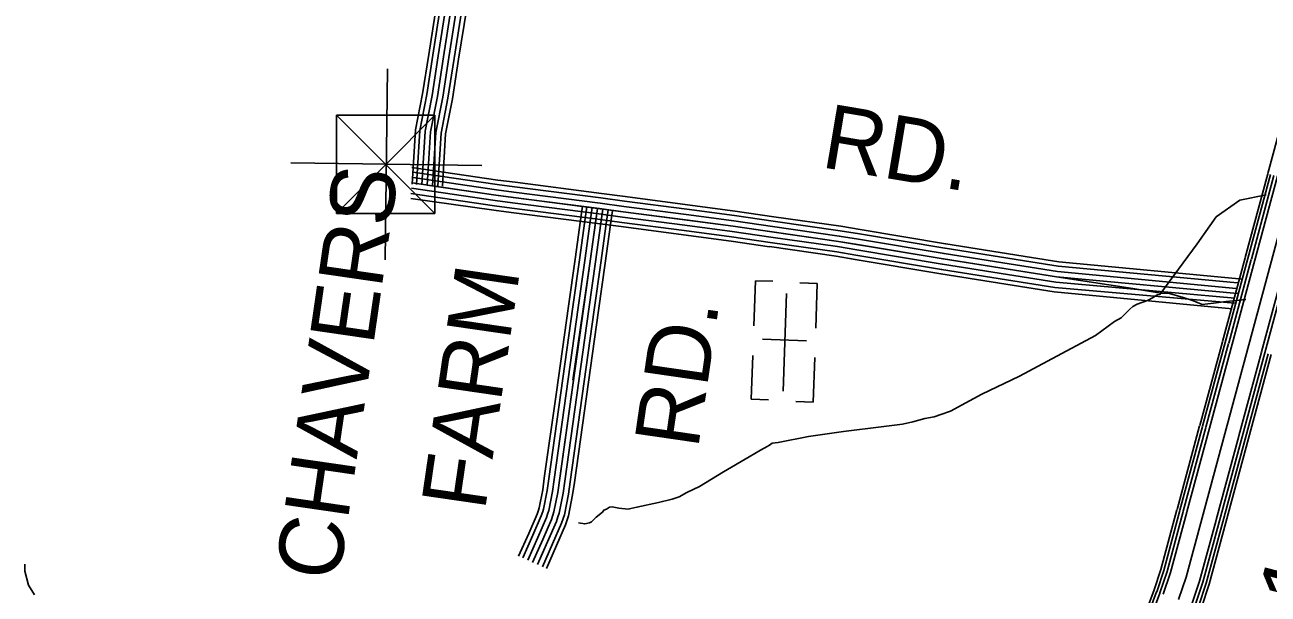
# Model space of a CAD drawing. Extents: x 1551132 to 1791609, y 378168 to 563823.
# Drawn here: x 1594362 to 1601513, y 424575 to 427854 of the extents above; entities that cross this region are included whole.
import ezdxf

# ---------------------------------------------------------------- set-up
doc = ezdxf.new("R2010")
doc.units = 0
for name, color, linetype in [('DESIGN - ROW - Right-of-Way and Easement Labels', 7, 'Continuous'), ('DESIGN - TRAFFIC CONTROL PERMANENT - Pavement Marking', 7, 'Continuous'), ('DESIGN - TRAFFIC CONTROL PERMANENT - Signalization', 7, 'Continuous'), ('DESIGN - TRANSPORTATION - Text', 7, 'Continuous'), ('DESIGN - UTILITIES - Cable (Underground) with Text', 7, 'Continuous'), ('SURVEY - CENTERLINE - Preliminary Text', 7, 'Continuous'), ('SURVEY - DRAINAGE - Bridge Hydraulic Data - Points - Locators', 7, 'Continuous'), ('SURVEY - PROPERTY - Owners', 7, 'Continuous'), ('SURVEY - TRANSPORTATION - Roads', 7, 'Continuous')]:
    doc.layers.add(name, color=color, linetype=linetype)

msp = doc.modelspace()

# ---------------------------------------------------------------- linework, layer by layer
at = {"layer": 'DESIGN - TRAFFIC CONTROL PERMANENT - Pavement Marking'}
for p, q in [((1596720.792, 427332.949), (1596155.091, 427332.935)), ((1596437.948, 427050.091), (1596155.091, 427332.935)), ((1596155.091, 427332.935), (1596155.105, 426767.233)), ((1596437.948, 427050.091), (1596720.792, 427332.949)), ((1596720.806, 426767.247), (1596720.792, 427332.949)), ((1596155.105, 426767.233), (1596437.948, 427050.091)), ((1596437.948, 427050.091), (1596720.806, 426767.247)), ((1596155.105, 426767.233), (1596720.806, 426767.247))]:
    msp.add_line(p, q, dxfattribs=at)
at = {"layer": 'DESIGN - TRANSPORTATION - Text'}
for points in [[(1597546.754, 424986.179), (1597582.628, 424979.612), (1597608.703, 424985.221), (1597620.786, 424991.038), (1597647.193, 425018.68), (1597683.626, 425048.173), (1597691.776, 425058.065), (1597707.859, 425063.831), (1597724.025, 425075.598), (1597740.041, 425077.357), (1597777.915, 425070.757), (1597831.781, 425063.915), (1597847.822, 425067.673), (1597881.921, 425075.165), (1598006.277, 425103.291), (1598084.517, 425122.116), (1598124.699, 425135.525), (1598169.065, 425160.884), (1598241.563, 425195.827), (1598380.776, 425279.829), (1598528.015, 425365.706), (1598592.58, 425404.783), (1598630.887, 425426.233), (1598644.995, 425434.025), (1598661.137, 425443.792), (1598695.203, 425449.284), (1598869.607, 425482.643), (1599069.927, 425511.602), (1599288.205, 425538.286), (1599410.378, 425554.429), (1599468.543, 425567.554), (1599538.791, 425586.505), (1599592.898, 425595.68), (1599631.081, 425609.114), (1599685.346, 425628.314), (1599774.044, 425677.032), (1599866.775, 425727.692), (1600082.229, 425830.553), (1600243.45, 425916.214), (1600519.569, 426064.218), (1600628.749, 426144.678), (1600667.057, 426166.129), (1600685.323, 426183.879), (1600717.789, 426215.43), (1600734.022, 426231.214), (1600760.213, 426244.831), (1600818.503, 426265.973), (1600852.753, 426283.474), (1600874.985, 426299.157), (1600891.002, 426300.916), (1601104.63, 426592.082), (1601213.628, 426747.228), (1601350.116, 426844.689), (1601502.063, 426874.673)], [(1594362.12, 424747.754), (1594361.67, 424707.703), (1594382.778, 424627.351), (1594416.144, 424570.883)]]:
    msp.add_lwpolyline(points, dxfattribs=at)
at = {"layer": 'DESIGN - UTILITIES - Cable (Underground) with Text'}
for p, q in [((1598563.915, 426380.045), (1598554.81, 426119.381)), ((1598663.534, 426376.572), (1598564.531, 426380.045)), ((1598919.931, 426363.683), (1598820.221, 426367.157)), ((1598910.868, 426107.069), (1598919.84, 426363.683)), ((1598858.284, 426034.466), (1598604.795, 426043.305)), ((1598548.87, 425948.527), (1598540.073, 425697.238)), ((1598895.998, 425680.834), (1598905.02, 425938.806)), ((1598540.206, 425697.238), (1598638.417, 425693.806)), ((1598895.823, 425680.834), (1598796.379, 425684.308))]:
    msp.add_line(p, q, dxfattribs=at)
msp.add_lwpolyline([(1598742.386, 426306.388), (1598722.727, 425743.708)], dxfattribs=at)
at = {"layer": 'SURVEY - CENTERLINE - Preliminary Text'}
for points in [[(1600998.398, 424544.753), (1601040.98, 424673.207), (1601887.204, 427811.148)], [(1601510.788, 426997.068), (1601640.985, 427479.831)], [(1601380.365, 426513.422), (1601510.554, 426996.184)], [(1601397.265, 426508.863), (1601527.454, 426991.626)], [(1601416.573, 426503.655), (1601546.762, 426986.418)], [(1601436.389, 426499.246), (1601566.578, 426982.017)], [(1601249.943, 426029.784), (1601380.132, 426512.547)], [(1601266.843, 426025.225), (1601397.032, 426507.988)], [(1601286.151, 426020.017), (1601416.339, 426502.78)], [(1601305.967, 426015.609), (1601436.156, 426498.371)], [(1601474.379, 425970.191), (1601604.568, 426452.954)], [(1601493.962, 425964.907), (1601624.151, 426447.67)], [(1601119.512, 425546.138), (1601249.701, 426028.901)], [(1601136.412, 425541.579), (1601266.601, 426024.342)], [(1601155.72, 425536.371), (1601285.909, 426019.134)], [(1601175.536, 425531.962), (1601305.733, 426014.734)], [(1601343.949, 425486.545), (1601474.146, 425969.316)], [(1601363.532, 425481.261), (1601493.729, 425964.032)], [(1601382.84, 425476.053), (1601513.037, 425958.824)], [(1601399.739, 425471.494), (1601529.936, 425954.265)], [(1600989.09, 425062.492), (1601119.279, 425545.263)], [(1601005.99, 425057.933), (1601136.179, 425540.704)], [(1601025.298, 425052.725), (1601155.487, 425535.496)], [(1601045.114, 425048.325), (1601175.303, 425531.087)], [(1601213.527, 425002.907), (1601343.716, 425485.67)], [(1601233.109, 424997.624), (1601363.298, 425480.386)], [(1601252.417, 424992.415), (1601382.606, 425475.178)], [(1601269.317, 424987.857), (1601399.506, 425470.619)], [(1600855.451, 424594.938), (1600855.56, 424595.221), (1600895.859, 424716.791), (1600988.849, 425061.617)], [(1600871.834, 424588.788), (1600872.059, 424589.388), (1600912.625, 424711.757), (1601005.748, 425057.058)], [(1600890.559, 424581.762), (1600890.926, 424582.721), (1600931.791, 424705.999), (1601025.056, 425051.85)], [(1600909.9, 424575.562), (1600910.067, 424576.012), (1600951.224, 424700.166), (1601044.881, 425047.441)], [(1601073.146, 424514.111), (1601074.538, 424517.811), (1601118.345, 424649.973), (1601213.293, 425002.024)], [(1601092.129, 424506.969), (1601093.662, 424511.044), (1601137.778, 424644.131), (1601232.876, 424996.74)], [(1601110.845, 424499.919), (1601112.52, 424504.377), (1601156.944, 424638.372), (1601252.184, 424991.532)], [(1601127.22, 424493.752), (1601129.02, 424498.535), (1601173.711, 424633.339), (1601269.084, 424986.973)], [(1600635.373, 424194.36), (1600709.038, 424294.738), (1600784.786, 424425.483), (1600816.744, 424492.193), (1600855.193, 424594.254)], [(1600649.481, 424184.002), (1600723.704, 424285.146), (1600800.269, 424417.3), (1600832.852, 424485.31), (1600871.568, 424588.088)], [(1600665.606, 424172.176), (1600740.462, 424274.188), (1600817.969, 424407.958), (1600851.268, 424477.451), (1600890.284, 424581.037)]]:
    msp.add_lwpolyline(points, dxfattribs=at)
at = {"layer": 'SURVEY - DRAINAGE - Bridge Hydraulic Data - Points - Locators'}
for p, q in [((1596448.465, 427600.864), (1596433.94, 426500.927)), ((1596991.143, 427043.633), (1595891.261, 427058.158))]:
    msp.add_line(p, q, dxfattribs=at)
at = {"layer": 'SURVEY - PROPERTY - Owners'}
for points in [[(1596675.742, 426930.705), (1596694.817, 427237.438), (1596734.408, 427441.635), (1596770.182, 427669.924), (1596816.465, 427964.299), (1596839.523, 428100.452), (1596849.914, 428150.495), (1596850.214, 428190.596), (1596846.789, 428268.815), (1596830.056, 428441.386), (1596797.582, 428654.183), (1596781.891, 428698.426), (1596764.067, 428726.635), (1596752.125, 428736.76), (1596736.159, 428744.902), (1596714.151, 428749.094), (1596684.085, 428747.327), (1596611.853, 428733.877), (1596426.283, 428692.617)], [(1597514.189, 425807.442), (1597613.745, 426492.169), (1597655.961, 426796.543)]]:
    msp.add_lwpolyline(points, dxfattribs=at)
at = {"layer": 'SURVEY - TRANSPORTATION - Roads'}
for points in [[(1596763.29, 426925.263), (1596782.007, 427226.321), (1596820.823, 427426.493), (1596856.839, 427656.324), (1596903.038, 427950.165), (1596925.737, 428084.202), (1596937.562, 428141.162), (1596937.945, 428192.188), (1596934.321, 428274.973), (1596917.129, 428452.245), (1596883.039, 428675.651), (1596861.281, 428736.994), (1596831.04, 428784.853), (1596801.066, 428810.271), (1596764.858, 428828.73), (1596719.868, 428837.296), (1596673.444, 428834.571), (1596594.304, 428819.838), (1596407.25, 428778.245)], [(1596737.624, 426926.855), (1596756.449, 427229.579), (1596795.49, 427430.935), (1596831.431, 427660.307), (1596877.655, 427954.307), (1596900.463, 428088.969), (1596911.863, 428143.895), (1596912.221, 428191.721), (1596908.655, 428273.165), (1596891.605, 428449.061), (1596857.981, 428669.359), (1596838.006, 428725.685), (1596811.407, 428767.786), (1596786.716, 428788.72), (1596756.442, 428804.154), (1596718.193, 428811.437), (1596676.56, 428808.996), (1596599.445, 428794.637), (1596412.825, 428753.144)], [(1596706.683, 426928.78), (1596725.633, 427233.513), (1596764.949, 427436.285), (1596800.807, 427665.116), (1596847.056, 427959.298), (1596869.989, 428094.71), (1596880.888, 428147.195), (1596881.222, 428191.155), (1596877.722, 428270.99), (1596860.831, 428445.22), (1596827.782, 428661.775), (1596809.949, 428712.06), (1596787.733, 428747.211), (1596769.425, 428762.736), (1596746.3, 428774.528), (1596716.176, 428780.27), (1596680.327, 428778.161), (1596605.654, 428764.253), (1596419.558, 428722.877)], [(1596675.742, 426930.705), (1596694.817, 427237.438), (1596734.408, 427441.635), (1596770.182, 427669.924), (1596816.465, 427964.299), (1596839.523, 428100.452), (1596849.914, 428150.495), (1596850.214, 428190.596), (1596846.789, 428268.815), (1596830.056, 428441.386), (1596797.582, 428654.183), (1596781.891, 428698.426), (1596764.067, 428726.635), (1596752.125, 428736.76), (1596736.159, 428744.902), (1596714.151, 428749.094), (1596684.085, 428747.327), (1596611.853, 428733.877), (1596426.283, 428692.617)], [(1596675.742, 426930.705), (1596694.817, 427237.438), (1596734.408, 427441.635), (1596770.182, 427669.924), (1596816.465, 427964.299), (1596839.523, 428100.452), (1596849.914, 428150.495), (1596850.214, 428190.596), (1596846.789, 428268.815), (1596830.056, 428441.386), (1596797.582, 428654.183), (1596781.891, 428698.426), (1596764.067, 428726.635), (1596752.125, 428736.76), (1596736.159, 428744.902), (1596714.151, 428749.094), (1596684.085, 428747.327), (1596611.853, 428733.877), (1596426.283, 428692.617)], [(1596644.802, 426932.63), (1596664.001, 427241.363), (1596703.867, 427446.985), (1596739.558, 427674.733), (1596785.874, 427969.299), (1596809.057, 428106.194), (1596818.94, 428153.795), (1596819.207, 428190.038), (1596815.857, 428266.64), (1596799.282, 428437.553), (1596767.383, 428646.591), (1596753.833, 428684.792), (1596740.4, 428706.06), (1596734.826, 428710.785), (1596726.017, 428715.277), (1596712.126, 428717.918), (1596687.843, 428716.493), (1596618.053, 428703.501), (1596433.008, 428662.358)], [(1596613.861, 426934.555), (1596633.185, 427245.296), (1596673.326, 427452.335), (1596708.934, 427679.541), (1596755.275, 427974.29), (1596778.582, 428111.936), (1596787.966, 428157.095), (1596788.207, 428189.471), (1596784.924, 428264.465), (1596768.508, 428433.711), (1596737.184, 428639.008), (1596725.776, 428671.167), (1596716.984, 428685.084), (1596715.876, 428685.651), (1596710.109, 428686.751), (1596691.61, 428685.659), (1596624.261, 428673.117), (1596439.741, 428632.091)], [(1596589.194, 426936.088), (1596608.619, 427248.43), (1596648.985, 427456.61), (1596684.518, 427683.374), (1596730.884, 427978.274), (1596754.291, 428116.511), (1596763.266, 428159.729), (1596763.483, 428189.021), (1596760.258, 428262.731), (1596743.975, 428430.652), (1596713.101, 428632.958), (1596703.41, 428660.3), (1596702.618, 428661.55), (1596694.61, 428661.075), (1596629.203, 428648.9), (1596445.099, 428607.965)], [(1596587.303, 427031.666), (1597082.7, 426959.647), (1597181.972, 426946.722)], [(1596593.619, 427005.415), (1597079.166, 426934.172), (1597178.647, 426921.221)], [(1596595.911, 426973.756), (1597074.916, 426903.463), (1597174.647, 426890.479)], [(1597181.956, 426946.722), (1597677.761, 426882.162)], [(1596582.761, 426881.687), (1597062.167, 426811.335), (1597162.648, 426798.252)], [(1596585.295, 426912.637), (1597066.417, 426842.044), (1597166.648, 426828.994)], [(1596589.703, 426943.33), (1597070.667, 426872.753), (1597170.647, 426859.736)], [(1596675.742, 426930.705), (1597070.667, 426872.753), (1597802.883, 426777.41), (1598435.318, 426693.883), (1599041.687, 426606.814), (1599643.814, 426505.795), (1600295.874, 426401.868), (1600734.647, 426335.85), (1600896.143, 426308.891), (1600946.092, 426305.991), (1601023.657, 426282.549), (1601083.305, 426263.44), (1601134.529, 426243.264), (1601199.078, 426251.331), (1601271.234, 426260.057), (1601383.982, 426272.432)], [(1597174.631, 426890.479), (1597670.436, 426825.919)], [(1597178.639, 426921.221), (1597674.444, 426856.662)], [(1597677.744, 426882.162), (1597814.291, 426864.387), (1598173.616, 426816.919)], [(1596582.378, 426852.811), (1597058.775, 426786.851), (1597159.456, 426773.743)], [(1597166.631, 426828.994), (1597662.436, 426764.434)], [(1597170.631, 426859.736), (1597666.436, 426795.177)], [(1597557.897, 426727.967), (1597569.08, 426808.594)], [(1597583.371, 426724.433), (1597594.554, 426805.06)], [(1597614.07, 426720.175), (1597625.253, 426800.802)], [(1597670.419, 426825.919), (1597806.916, 426808.144), (1598166.191, 426760.693)], [(1597674.427, 426856.662), (1597810.941, 426838.886), (1598170.249, 426791.427)], [(1598173.599, 426816.928), (1598447.293, 426780.785), (1598669.921, 426748.81)], [(1597159.431, 426773.743), (1597655.236, 426709.183)], [(1597162.623, 426798.252), (1597658.428, 426733.692)], [(1597282.227, 424758.315), (1597340.467, 424889.618), (1597390.441, 425005.021), (1597398.891, 425030.939), (1597405.191, 425048.872), (1597426.79, 425161.142), (1597613.745, 426492.169), (1597655.961, 426796.543)], [(1597644.778, 426715.916), (1597655.961, 426796.543)], [(1597658.411, 426733.692), (1597794.824, 426715.933), (1598154.016, 426668.49)], [(1597662.419, 426764.434), (1597798.849, 426746.676), (1598158.074, 426699.225)], [(1597666.419, 426795.177), (1597802.883, 426777.41), (1598162.133, 426729.959)], [(1597675.486, 426711.658), (1597686.669, 426792.285)], [(1597706.185, 426707.399), (1597717.368, 426788.027)], [(1597730.668, 426703.999), (1597741.851, 426784.627)], [(1598162.116, 426729.967), (1598435.318, 426693.883), (1598657.454, 426661.982)], [(1598166.174, 426760.701), (1598439.551, 426724.592), (1598661.862, 426692.666)], [(1598170.232, 426791.435), (1598443.784, 426755.301), (1598666.271, 426723.351)], [(1598669.904, 426748.818), (1599055.178, 426693.492), (1599166.467, 426674.825)], [(1597488.756, 426232.92), (1597526.872, 426504.294), (1597557.897, 426727.983)], [(1597514.222, 426229.345), (1597552.338, 426500.736), (1597583.371, 426724.45)], [(1597544.922, 426225.028), (1597583.046, 426496.452), (1597614.07, 426720.191)], [(1597575.621, 426220.72), (1597613.745, 426492.169), (1597644.778, 426715.933)], [(1597606.32, 426216.412), (1597644.444, 426487.885), (1597675.486, 426711.675)], [(1597637.019, 426212.095), (1597675.152, 426483.602), (1597706.185, 426707.416)], [(1597655.228, 426709.183), (1597791.608, 426691.424), (1598150.774, 426643.99)], [(1597661.494, 426208.661), (1597699.627, 426480.185), (1597730.668, 426704.016)], [(1598153.999, 426668.499), (1598426.851, 426632.465), (1598648.638, 426600.614)], [(1598158.058, 426699.233), (1598431.085, 426663.174), (1598653.046, 426631.298)], [(1598657.438, 426661.991), (1599041.687, 426606.814), (1599151.951, 426588.314)], [(1598661.846, 426692.675), (1599046.453, 426637.448), (1599157.084, 426618.89)], [(1598666.246, 426723.359), (1599051.22, 426668.083), (1599162.209, 426649.457)], [(1599166.451, 426674.833), (1599657.897, 426592.381), (1599658.681, 426592.256)], [(1598150.758, 426643.998), (1598423.476, 426607.972), (1598645.129, 426576.147)], [(1598648.629, 426600.622), (1599032.154, 426545.546), (1599141.693, 426527.171)], [(1598653.029, 426631.306), (1599036.92, 426576.18), (1599146.818, 426557.738)], [(1599151.934, 426588.322), (1599643.814, 426505.795), (1599645.031, 426505.604)], [(1599157.067, 426618.898), (1599648.789, 426536.396), (1599649.856, 426536.23)], [(1599162.192, 426649.466), (1599653.764, 426566.997), (1599654.681, 426566.847)], [(1599658.822, 426592.231), (1600152.577, 426513.538)], [(1598645.113, 426576.155), (1599028.345, 426521.12), (1599137.601, 426502.787)], [(1599141.676, 426527.179), (1599633.865, 426444.594), (1599635.381, 426444.36)], [(1599146.801, 426557.746), (1599638.839, 426475.195), (1599640.206, 426474.978)], [(1599649.889, 426536.221), (1600143.644, 426457.528)], [(1599654.772, 426566.83), (1600148.527, 426488.137)], [(1599137.585, 426502.795), (1599629.89, 426420.201), (1599631.54, 426419.943)], [(1599635.256, 426444.377), (1600129.011, 426365.684)], [(1599640.139, 426474.986), (1600133.894, 426396.293)], [(1599645.014, 426505.604), (1600138.769, 426426.91)], [(1600143.628, 426457.528), (1600300.616, 426432.502), (1601329.516, 426334.9)], [(1600148.511, 426488.137), (1600305.365, 426463.136), (1601337.241, 426367.385)], [(1600152.561, 426513.538), (1600309.299, 426488.554), (1601365.566, 426389.877)], [(1599631.365, 426419.968), (1600125.12, 426341.275)], [(1600133.878, 426396.293), (1600291.132, 426371.234), (1601321.792, 426279.924)], [(1600138.753, 426426.91), (1600295.874, 426401.868), (1601337.241, 426307.408)], [(1600125.103, 426341.275), (1600282.599, 426316.174), (1601306.334, 426217.447)], [(1600128.995, 426365.684), (1600286.383, 426340.6), (1601321.792, 426249.931)], [(1597419.208, 425737.791), (1597488.756, 426232.937)], [(1597444.674, 425734.215), (1597514.222, 426229.362)], [(1597475.373, 425729.899), (1597544.922, 426225.045)], [(1597506.072, 425725.59), (1597575.621, 426220.737)], [(1597536.772, 425721.282), (1597606.32, 426216.428)], [(1597567.471, 425716.965), (1597637.019, 426212.111)], [(1597591.945, 425713.532), (1597661.494, 426208.678)], [(1597349.659, 425242.652), (1597419.208, 425737.807)], [(1597375.125, 425239.077), (1597444.674, 425734.232)], [(1597405.824, 425234.761), (1597475.373, 425729.915)], [(1597436.524, 425230.452), (1597506.072, 425725.607)], [(1597467.223, 425226.144), (1597536.772, 425721.298)], [(1597497.922, 425221.827), (1597567.471, 425716.982)], [(1597522.397, 425218.394), (1597591.945, 425713.548)], [(1597202.045, 424793.882), (1597260.128, 424924.836), (1597308.318, 425036.114), (1597315.801, 425059.073), (1597320.285, 425071.823), (1597340.234, 425175.542), (1597349.667, 425242.677)], [(1597225.553, 424783.457), (1597283.685, 424914.51), (1597332.393, 425026.997), (1597340.167, 425050.822), (1597345.176, 425065.089), (1597365.617, 425171.317), (1597375.133, 425239.094)], [(1597253.894, 424770.882), (1597312.076, 424902.06), (1597361.417, 425016.013), (1597369.525, 425040.881), (1597375.183, 425056.981), (1597396.199, 425166.234), (1597405.833, 425234.786)], [(1597282.227, 424758.315), (1597340.467, 424889.618), (1597390.441, 425005.021), (1597398.891, 425030.939), (1597405.191, 425048.872), (1597426.79, 425161.142), (1597436.532, 425230.469)], [(1597310.56, 424745.748), (1597368.858, 424877.176), (1597419.465, 424994.029), (1597428.257, 425020.997), (1597435.198, 425040.764), (1597457.381, 425156.05), (1597467.231, 425226.152)], [(1597338.901, 424733.172), (1597397.249, 424864.726), (1597448.49, 424983.046), (1597457.615, 425011.055), (1597465.206, 425032.655), (1597487.964, 425150.967), (1597497.93, 425221.844)], [(1597361.492, 424723.156), (1597419.89, 424854.809), (1597471.631, 424974.279), (1597481.031, 425003.121), (1597489.131, 425026.189), (1597512.355, 425146.908), (1597522.405, 425218.402)]]:
    msp.add_lwpolyline(points, dxfattribs=at)

# ---------------------------------------------------------------- texts
at = {"layer": 'DESIGN - ROW - Right-of-Way and Easement Labels'}
for s, height, rotation, p in [('RD.', 369.9918, 350.4759722, (1598934.331, 427035.217)), ('CHAVERS', 370.0094, 81.7276556, (1596167.395, 424641.878)), ('FARM', 370.0094, 81.7276556, (1597007.883, 425049.614)), ('RD.', 370.0094, 81.7276556, (1598233.457, 425405.801))]:
    msp.add_text(s, height=height, rotation=rotation, dxfattribs=at).set_placement(p)
at = {"layer": 'DESIGN - TRAFFIC CONTROL PERMANENT - Signalization'}
msp.add_text('6.1', height=370.0087, rotation=75.5150333, dxfattribs=at).set_placement((1601707.574, 424074.512))

doc.saveas('drawing.dxf')
